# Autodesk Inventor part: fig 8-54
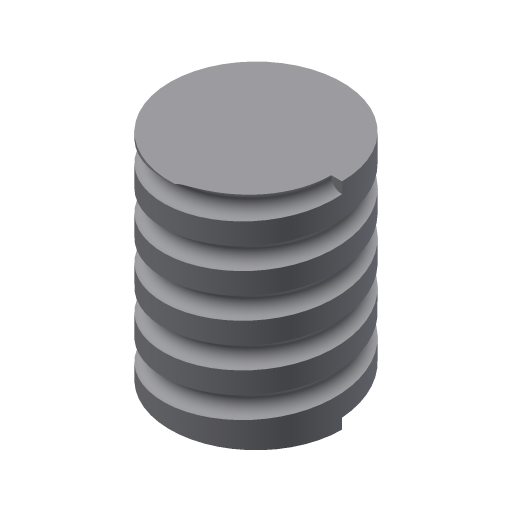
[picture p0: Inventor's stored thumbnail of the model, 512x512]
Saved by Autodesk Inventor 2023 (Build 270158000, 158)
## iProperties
Created: 2002-01
Part Number: fig 8-54
Document SubType Name: Modeling
Designer: CADSoft
Density: 1 g/cm^3
Material: Generic
Appearance: Default
Control State: 0
Master: False
Checked Out: False
Shininess: 77.0
Length Units: 11269
Angle Units: 11279
Time Units: 11290
Mass Units: 11283
Length Display Precision: 3
Angle Display Precision: 2
Density: 0.0
Volumn: 0.0
Area: 0.0
PropertySet Name: Model Information
Author: CADSoft
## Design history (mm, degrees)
sketch "Sketch4"
  geometry: C1 r 20 at (0, 0)
  constraints: 1 centre point
  dimensions: "d44" = 40 diameter of C1
sketch "Sketch2"
  geometry: C1 r 2.5 at (-20, -0.092); 1 further point
  constraints: 1 centre point, 1 other
  dimensions: "d0" = 5 diameter of C1; "d43" = 20 horizontal distance of C1.centre point (0, 0)
extrude "Extrusion2" join sketch "Sketch4" distance "d45" = 50; taper "d46" = 0 deg
coil "Coil6" pitch "d47" = 10; turns "d49" = 5; dims "d48" = 10, "d50" = 0, angle "d51" = 90 deg, angle "d52" = 90 deg, "d53" = 0, "d54" = 0
body "Solid1"
